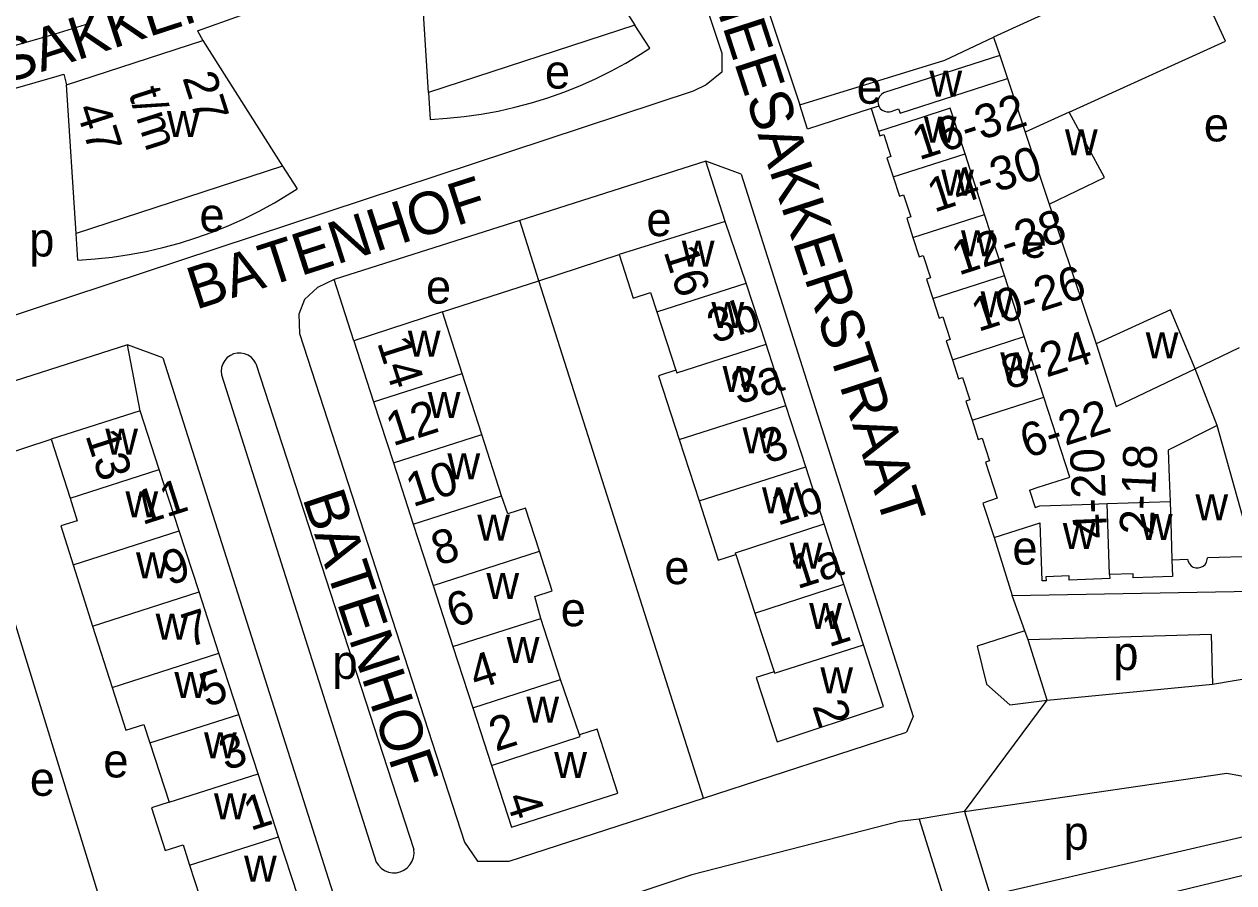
# Model space of a CAD drawing. Extents: x 159261 to 160849, y 382514 to 384534.
# Drawn here: x 159465.8 to 159608.7, y 383871.6 to 383973 of the extents above; entities that cross this region are included whole.
import ezdxf

# ---------------------------------------------------------------- set-up
doc = ezdxf.new("R2010")
doc.units = 0
for name, color, linetype in [('BLT_Basislijn', 7, 'Continuous'), ('BLT_Bebouwing', 7, 'Continuous'), ('BLT_Centroide', 7, 'Continuous'), ('BLT_Huisnummer', 7, 'Continuous'), ('BLT_Huisnummer_ tussenligend', 7, 'Continuous'), ('BLT_Huisnummer_reeks', 7, 'Continuous'), ('BLT_Onderverdeling_panden', 7, 'Continuous'), ('BLT_Straatnaam', 7, 'Continuous'), ('BLT_Vlakafsluiter', 7, 'Continuous')]:
    doc.layers.add(name, color=color, linetype=linetype)

msp = doc.modelspace()

# ---------------------------------------------------------------- linework, layer by layer
at = {"layer": 'BLT_Basislijn'}
for p, q in [((159486.27, 383972.23), (159486.92, 383971.08)), ((159539.7, 383970.18), (159537.94, 383972.9)), ((159470.51, 383967.12), (159470.82, 383965.85)), ((159513.56, 383964.95), (159513.76, 383961.78)), ((159566.75, 383963.34), (159565.83, 383963.05)), ((159565.83, 383963.05), (159566.72, 383960.35)), ((159546.3, 383956.85), (159524.34, 383949.84)), ((159550.49, 383955.29), (159546.3, 383956.85)), ((159548.59, 383949.7), (159546.3, 383956.85)), ((159496.32, 383956.25), (159498.05, 383953.56)), ((159586.88, 383951.77), (159592.41, 383935.27)), ((159526.61, 383942.71), (159524.34, 383949.84)), ((159472.15, 383945.16), (159471.94, 383948.3)), ((159526.61, 383942.71), (159536.09, 383945.81)), ((159504.74, 383935.61), (159502.43, 383942.85)), ((159515.2, 383939.05), (159526.61, 383942.71)), ((159546.06, 383881.62), (159526.61, 383942.71)), ((159478.01, 383935.15), (159456.04, 383928.14)), ((159482.19, 383933.6), (159478.01, 383935.15)), ((159479.51, 383927.34), (159478.01, 383935.15)), ((159604.09, 383932.33), (159609.33, 383934.84)), ((159606.71, 383925.63), (159604.09, 383932.33)), ((159459, 383920.75), (159469.01, 383924)), ((159477.76, 383859.92), (159459.94, 383917.82)), ((159580.37, 383912.39), (159582.49, 383905.53)), ((159584, 383901.36), (159582.49, 383905.53)), ((159584.39, 383900.29), (159584, 383901.36)), ((159605.98, 383900.92), (159584.39, 383900.29)), ((159605.98, 383900.92), (159606.15, 383895.08)), ((159586.64, 383893.19), (159584.39, 383900.29)), ((159546.06, 383881.62), (159570.02, 383889.39)), ((159576.87, 383880.02), (159571.53, 383879.14))]:
    msp.add_line(p, q, dxfattribs=at)
for points in [[(159539.48, 383995.83), (159548.21, 383969.61), (159548.21, 383967.35), (159546.34, 383965.85), (159544.84, 383965.1)], [(159486.27, 383972.23), (159491.37, 383974.05), (159496.45, 383975.95), (159501.49, 383977.92), (159506.5, 383979.96), (159511.49, 383982.08), (159512.44, 383982.5)], [(159559.38, 383977.05), (159553.49, 383975.26), (159557.4, 383963.49)], [(159432.92, 383963.01), (159438.12, 383964.03), (159443.3, 383965.12), (159448.47, 383966.29), (159453.62, 383967.53), (159458.75, 383968.86), (159463.86, 383970.26), (159468.95, 383971.74), (159473.57, 383973.15)], [(159557.4, 383963.49), (159574.56, 383968.78), (159580.29, 383971.51)], [(159513.76, 383961.78), (159515.78, 383961.91), (159517.79, 383962.11), (159519.79, 383962.4), (159521.78, 383962.76), (159523.76, 383963.21), (159525.71, 383963.73), (159527.64, 383964.33), (159529.55, 383965), (159531.43, 383965.75), (159533.28, 383966.58), (159535.09, 383967.47), (159536.87, 383968.44), (159538.61, 383969.47), (159539.7, 383970.18)], [(159443.48, 383960.15), (159448.77, 383961.34), (159454.03, 383962.61), (159459.27, 383963.96), (159464.5, 383965.38), (159469.7, 383966.88), (159470.51, 383967.12)], [(159544.84, 383965.1), (159432.28, 383927.93), (159430.03, 383927.56), (159427.78, 383927.93), (159425.9, 383928.68), (159423.65, 383935.07), (159417.03, 383955.37)], [(159565.83, 383963.05), (159558.32, 383960.64), (159557.4, 383963.49)], [(159550.49, 383955.29), (159570.82, 383891.26), (159570.02, 383889.39)], [(159472.15, 383945.16), (159474.18, 383945.3), (159476.2, 383945.51), (159478.22, 383945.81), (159480.21, 383946.18), (159482.2, 383946.64), (159484.16, 383947.17), (159486.1, 383947.77), (159488.02, 383948.46), (159489.9, 383949.21), (159491.76, 383950.04), (159493.58, 383950.95), (159495.37, 383951.92), (159497.11, 383952.97), (159498.05, 383953.56)], [(159524.34, 383949.84), (159502.43, 383942.85)], [(159502.43, 383942.85), (159500.47, 383941.93), (159498.92, 383940.52), (159498.25, 383938.79), (159498.33, 383936.49), (159517.83, 383876.42), (159519.34, 383874.17), (159523.09, 383874.17), (159546.06, 383881.62)], [(159493.16, 383932.96), (159492.95, 383933.32), (159492.65, 383933.64), (159492.27, 383933.91), (159491.84, 383934.09), (159491.39, 383934.17), (159490.95, 383934.16), (159490.54, 383934.07), (159490.16, 383933.9), (159489.8, 383933.64), (159489.49, 383933.3), (159489.26, 383932.9), (159489.12, 383932.46), (159489.08, 383932.02), (159489.12, 383931.6)], [(159482.19, 383933.6), (159502.53, 383869.56), (159501.72, 383867.69)], [(159493.16, 383932.96), (159511.82, 383875.52)], [(159489.12, 383931.6), (159507.39, 383874.05)], [(159582.49, 383905.53), (159610.88, 383906.06), (159611.04, 383910.16)], [(159584, 383901.36), (159578.35, 383899.57), (159579.47, 383895.05), (159582.22, 383892.62), (159586.64, 383893.19)], [(159586.64, 383893.19), (159606.15, 383895.08)], [(159606.15, 383895.08), (159611.26, 383895.92)], [(159576.87, 383880.02), (159607.84, 383884.57), (159613.4, 383883.55), (159615.78, 383881.39), (159617.5, 383878.84)], [(159576.87, 383880.02), (159579.79, 383870.52), (159580.1, 383870.2), (159617.5, 383878.84)], [(159571.53, 383879.14), (159574.49, 383869.54), (159573.51, 383869.33), (159573.04, 383868.91), (159539.85, 383861.58), (159533.8, 383859.61), (159521.41, 383853.83), (159520.77, 383854.16), (159518.2, 383863.73)], [(159571.53, 383879.14), (159569.17, 383878.86), (159544.68, 383872.53), (159518.2, 383863.73)], [(159507.39, 383874.05), (159507.64, 383873.67), (159507.97, 383873.33), (159508.38, 383873.06), (159508.84, 383872.87), (159509.32, 383872.79), (159509.79, 383872.8), (159510.23, 383872.9), (159510.64, 383873.08), (159511.03, 383873.36), (159511.37, 383873.71), (159511.62, 383874.14), (159511.79, 383874.6), (159511.85, 383875.07), (159511.82, 383875.52)], [(159585.27, 383853.34), (159584.12, 383856.18), (159581.66, 383865.68), (159618.88, 383874.73)]]:
    msp.add_lwpolyline(points, dxfattribs=at)
at = {"layer": 'BLT_Bebouwing'}
for p, q in [((159528.54, 383987.73), (159537.94, 383972.9)), ((159513.56, 383964.95), (159512.44, 383982.5)), ((159537.94, 383972.9), (159513.56, 383964.95)), ((159470.82, 383965.85), (159486.92, 383971.08)), ((159486.92, 383971.08), (159496.32, 383956.25)), ((159580.29, 383971.51), (159581.04, 383969.34)), ((159581.04, 383969.34), (159567.31, 383964.9)), ((159581.93, 383966.6), (159582.48, 383964.94)), ((159471.94, 383948.3), (159470.82, 383965.85)), ((159582.48, 383964.94), (159584.04, 383960.27)), ((159579.24, 383950.56), (159576.93, 383957.73)), ((159496.32, 383956.25), (159471.94, 383948.3)), ((159548.59, 383949.7), (159536.09, 383945.81)), ((159581.58, 383943.35), (159579.24, 383950.56)), ((159583.92, 383936.12), (159581.58, 383943.35)), ((159515.2, 383939.05), (159504.74, 383935.61)), ((159586.23, 383928.98), (159583.92, 383936.12)), ((159479.51, 383927.34), (159469.01, 383924)), ((159481.76, 383920.41), (159479.51, 383927.34)), ((159469.01, 383924), (159471.23, 383917.04)), ((159484.11, 383913.18), (159481.76, 383920.41)), ((159593.73, 383916.39), (159601.14, 383916.64)), ((159486.46, 383905.96), (159484.11, 383913.18)), ((159611.04, 383910.16), (159605.55, 383909.98)), ((159471.58, 383909.17), (159473.88, 383901.93)), ((159488.81, 383898.73), (159486.46, 383905.96)), ((159473.88, 383901.93), (159476.19, 383894.69)), ((159491.16, 383891.5), (159488.81, 383898.73)), ((159493.44, 383884.49), (159491.16, 383891.5)), ((159480.66, 383888.14), (159482.93, 383881.13)), ((159495.86, 383877.04), (159493.44, 383884.49))]:
    msp.add_line(p, q, dxfattribs=at)
for points in [[(159619.1, 383987.92), (159611.22, 383985.63), (159580.29, 383971.51)], [(159589.23, 383962.63), (159607.68, 383971.03), (159605.6, 383975.56)], [(159568.19, 383962.73), (159569.09, 383963.02), (159569.26, 383962.5), (159581.93, 383966.6)], [(159567.31, 383964.9), (159567.06, 383964.73), (159566.85, 383964.51), (159566.71, 383964.23), (159566.65, 383963.93), (159566.66, 383963.63), (159566.75, 383963.34)], [(159576.93, 383957.73), (159575.19, 383963.1), (159571.48, 383961.9), (159566.72, 383960.35)], [(159566.75, 383963.34), (159566.92, 383963.08), (159567.14, 383962.88), (159567.41, 383962.74), (159567.71, 383962.67), (159568.02, 383962.69), (159568.19, 383962.73)], [(159586.88, 383951.77), (159593.42, 383954.92), (159589.23, 383962.63)], [(159566.72, 383960.35), (159566.88, 383959.85), (159567.33, 383960), (159568.17, 383957.39), (159567.71, 383957.24), (159568.45, 383954.98)], [(159584.04, 383960.27), (159586.88, 383951.77)], [(159568.45, 383954.98), (159569.18, 383952.71), (159569.66, 383952.87), (159570.51, 383950.25), (159570.04, 383950.1), (159570.78, 383947.82)], [(159551.08, 383942.43), (159548.59, 383949.7)], [(159570.78, 383947.82), (159571.51, 383945.55), (159572, 383945.71), (159572.86, 383943.07), (159572.37, 383942.91), (159573.11, 383940.61)], [(159536.09, 383945.81), (159537.73, 383940.68), (159539.8, 383941.35), (159540.54, 383939.06)], [(159553.43, 383935.21), (159551.08, 383942.43)], [(159573.11, 383940.61), (159573.86, 383938.31), (159574.31, 383938.46), (159575.18, 383935.78), (159574.71, 383935.62), (159575.43, 383933.38)], [(159517.53, 383931.77), (159515.2, 383939.05)], [(159540.54, 383939.06), (159542.78, 383932.16)], [(159604.09, 383932.33), (159601.21, 383939.27), (159592.41, 383935.27)], [(159504.74, 383935.61), (159507.07, 383928.43)], [(159555.77, 383927.98), (159553.43, 383935.21)], [(159592.41, 383935.27), (159594.77, 383927.87), (159604.09, 383932.33)], [(159575.43, 383933.38), (159576.16, 383931.13), (159576.64, 383931.28), (159577.48, 383928.66), (159577.02, 383928.51), (159577.76, 383926.24)], [(159519.86, 383924.54), (159517.53, 383931.77)], [(159542.78, 383932.16), (159540.73, 383931.49), (159543.17, 383923.95)], [(159507.07, 383928.43), (159509.41, 383921.2)], [(159558.12, 383920.75), (159555.77, 383927.98)], [(159584.55, 383917.99), (159585.58, 383918.33), (159589.29, 383919.53), (159586.23, 383928.98)], [(159577.76, 383926.24), (159578.49, 383923.98), (159578.96, 383924.13), (159579.83, 383921.45), (159579.36, 383921.3), (159580.74, 383917.04), (159579.02, 383916.44), (159580.37, 383912.39)], [(159606.71, 383925.63), (159600.91, 383922.7), (159601.02, 383919.47), (159601.14, 383916.64)], [(159610.17, 383913.27), (159609.69, 383914.97), (159606.71, 383925.63)], [(159522.18, 383917.3), (159519.86, 383924.54)], [(159543.17, 383923.95), (159545.52, 383916.72)], [(159509.41, 383921.2), (159511.75, 383913.97)], [(159560.31, 383914), (159558.12, 383920.75)], [(159584.55, 383917.99), (159585.22, 383915.94), (159585.75, 383916.12), (159590.75, 383916.29), (159593.73, 383916.39)], [(159471.23, 383917.04), (159472.08, 383914.37), (159470.13, 383913.75), (159471.58, 383909.17)], [(159526.67, 383910.76), (159525.02, 383915.84), (159522.95, 383915.17), (159522.18, 383917.3)], [(159545.52, 383916.72), (159547.78, 383909.73), (159549.86, 383910.4)], [(159511.75, 383913.97), (159514.1, 383906.74)], [(159562.63, 383906.86), (159560.31, 383914)], [(159580.37, 383912.39), (159585.82, 383914.13)], [(159594.01, 383908.01), (159594.03, 383907.53), (159589.24, 383907.37), (159589.22, 383907.85), (159586.49, 383907.76), (159586.51, 383907.29), (159586.05, 383907.28), (159585.82, 383914.13)], [(159526.83, 383902.83), (159526.11, 383905.42), (159528.18, 383906.09), (159526.67, 383910.76)], [(159549.86, 383910.4), (159552.11, 383903.47)], [(159601.37, 383909.77), (159601.44, 383907.8), (159596.8, 383907.64), (159596.78, 383908.1), (159594.01, 383908.01)], [(159601.37, 383909.77), (159603.2, 383909.84), (159603.27, 383909.54), (159603.42, 383909.27), (159603.63, 383909.05), (159603.89, 383908.89), (159604.18, 383908.8), (159604.49, 383908.8), (159604.79, 383908.87), (159605.06, 383909.01), (159605.28, 383909.22), (159605.44, 383909.49), (159605.53, 383909.78), (159605.55, 383909.98)], [(159514.1, 383906.74), (159516.44, 383899.51)], [(159564.94, 383899.73), (159562.63, 383906.86)], [(159529.16, 383895.6), (159526.83, 383902.83)], [(159552.11, 383903.47), (159554.37, 383896.52)], [(159516.44, 383899.51), (159518.78, 383892.28)], [(159554.37, 383896.52), (159552.28, 383895.84), (159554.74, 383888.25), (159567.31, 383892.44), (159564.94, 383899.73)], [(159531.41, 383889.07), (159529.16, 383895.6)], [(159476.19, 383894.69), (159477.8, 383889.63), (159479.95, 383890.31), (159480.66, 383888.14)], [(159518.78, 383892.28), (159520.99, 383885.45)], [(159520.99, 383885.45), (159523.35, 383878.17), (159535.94, 383882.18), (159533.5, 383889.74), (159531.41, 383889.07)], [(159482.93, 383881.13), (159480.84, 383880.45), (159482.48, 383875.41), (159484.57, 383876.09), (159485.35, 383873.68)], [(159485.35, 383873.68), (159487.69, 383866.45), (159498.16, 383869.95), (159495.86, 383877.04)]]:
    msp.add_lwpolyline(points, dxfattribs=at)
at = {"layer": 'BLT_Onderverdeling_panden'}
for p, q in [((159581.04, 383969.34), (159581.93, 383966.6)), ((159589.23, 383962.63), (159584.04, 383960.27)), ((159568.45, 383954.98), (159576.93, 383957.73)), ((159570.78, 383947.82), (159579.24, 383950.56)), ((159540.54, 383939.06), (159551.08, 383942.43)), ((159573.11, 383940.61), (159581.58, 383943.35)), ((159575.43, 383933.38), (159583.92, 383936.12)), ((159507.07, 383928.43), (159517.53, 383931.77)), ((159543.17, 383923.95), (159555.77, 383927.98)), ((159577.76, 383926.24), (159586.23, 383928.98)), ((159509.41, 383921.2), (159519.86, 383924.54)), ((159471.23, 383917.04), (159481.76, 383920.41)), ((159545.52, 383916.72), (159558.12, 383920.75)), ((159511.75, 383913.97), (159522.18, 383917.3)), ((159594.01, 383908.01), (159593.73, 383916.39)), ((159471.58, 383909.17), (159484.11, 383913.18)), ((159514.1, 383906.74), (159526.67, 383910.76)), ((159552.11, 383903.47), (159562.63, 383906.86)), ((159473.88, 383901.93), (159486.46, 383905.96)), ((159516.44, 383899.51), (159526.83, 383902.83)), ((159476.19, 383894.69), (159488.81, 383898.73)), ((159518.78, 383892.28), (159529.16, 383895.6)), ((159480.66, 383888.14), (159491.16, 383891.5)), ((159482.93, 383881.13), (159493.44, 383884.49)), ((159485.35, 383873.68), (159495.86, 383877.04))]:
    msp.add_line(p, q, dxfattribs=at)
for points in [[(159542.78, 383932.16), (159542.89, 383931.83), (159553.43, 383935.21)], [(159601.14, 383916.64), (159601.27, 383912.8), (159601.37, 383909.77)], [(159549.86, 383910.4), (159549.81, 383910.58), (159560.31, 383914)], [(159554.37, 383896.52), (159554.42, 383896.35), (159564.94, 383899.73)], [(159520.99, 383885.45), (159531.47, 383888.9), (159531.41, 383889.07)]]:
    msp.add_lwpolyline(points, dxfattribs=at)
at = {"layer": 'BLT_Vlakafsluiter'}
msp.add_line((159576.87, 383880.02), (159586.64, 383893.19), dxfattribs=at)

# ---------------------------------------------------------------- texts
at = {"layer": 'BLT_Centroide'}
for s, p in [('e', (159527.31, 383965.42)), ('e', (159564.14, 383963.63)), ('w', (159572.72, 383964.45)), ('w', (159482.67, 383959.69)), ('e', (159605.13, 383959.18)), ('w', (159572.07, 383959.03)), ('w', (159588.73, 383957.53)), ('w', (159574.11, 383952.78)), ('e', (159486.51, 383948.51)), ('e', (159539.3, 383947.99)), ('p', (159466.4, 383945.59)), ('w', (159576.45, 383945.59)), ('e', (159583.62, 383945.43)), ('w', (159543.48, 383944.38)), ('e', (159513.26, 383940.02)), ('w', (159578.77, 383938.38)), ('w', (159546.98, 383937.12)), ('w', (159511.12, 383933.75)), ('w', (159598.27, 383933.56)), ('w', (159581.09, 383931.19)), ('w', (159548.3, 383929.56)), ('w', (159513.47, 383926.5)), ('w', (159475.39, 383922.19)), ('w', (159550.65, 383922.34)), ('w', (159515.8, 383919.25)), ('w', (159552.95, 383915.25)), ('w', (159477.77, 383914.78)), ('w', (159604.14, 383914.43)), ('w', (159519.32, 383912.03)), ('w', (159597.58, 383912.09)), ('w', (159588.47, 383911.05)), ('e', (159582.52, 383909.19)), ('w', (159556.21, 383908.72)), ('w', (159479.02, 383907.56)), ('e', (159541.41, 383906.88)), ('w', (159520.4, 383905.12)), ('e', (159529.18, 383901.91)), ('w', (159558.52, 383901.59)), ('w', (159481.34, 383900.31)), ('w', (159522.8, 383897.56)), ('p', (159594.44, 383896.73)), ('p', (159502.21, 383895.69)), ('w', (159483.55, 383893.44)), ('w', (159559.84, 383894)), ('w', (159525.12, 383890.53)), ('w', (159487.05, 383886.31)), ('e', (159475.16, 383884.05)), ('w', (159528.41, 383883.97)), ('e', (159466.48, 383881.88)), ('w', (159488.23, 383879.09)), ('p', (159588.56, 383875.5)), ('w', (159491.78, 383871.75))]:
    msp.add_text(s, height=4, dxfattribs=at).set_placement(p)
at = {"layer": 'BLT_Huisnummer'}
for s, rotation, p in [('16', 287.744, (159541.3, 383946.18)), ('3b', 17.7443, (159547.27, 383935.29)), ('14', 287.744, (159507.47, 383935.42)), ('12', 17.7443, (159509.35, 383923.15)), ('13', 287.744, (159473.01, 383924.47)), ('11', 17.7443, (159479.77, 383913.85)), ('1b', 17.7443, (159554.79, 383913.76)), ('8', 17.7443, (159514.68, 383909.01)), ('1', 17.7443, (159560.84, 383899.41)), ('5', 17.7443, (159487.31, 383892.33)), ('2', 287.744, (159558.86, 383892.5)), ('2', 17.7443, (159521.49, 383887.08)), ('1', 17.7443, (159492.54, 383877.72)), ('4', 287.744, (159522.63, 383881.66))]:
    msp.add_text(s, height=4, rotation=rotation, dxfattribs=at).set_placement(p)
at = {"layer": 'BLT_Huisnummer_ tussenligend'}
for s, p in [('3a', (159550.12, 383928.05)), ('3', (159553.55, 383921.08)), ('10', (159511.71, 383915.96)), ('9', (159482.88, 383906.69)), ('1a', (159557.12, 383906.27)), ('6', (159516.47, 383901.7)), ('7', (159485.24, 383899.38)), ('4', (159519.16, 383894.38)), ('3', (159489.61, 383884.83))]:
    msp.add_text(s, height=4, rotation=17.7443, dxfattribs=at).set_placement(p)
at = {"layer": 'BLT_Huisnummer_reeks'}
for s, rotation, p in [('27', 287.7057, (159484.47, 383966.71)), ('t/m', 287.7057, (159478.1, 383964.91)), ('16-32', 17.9511, (159571.5, 383956.93)), ('47', 287.7049, (159471.87, 383963.06)), ('14-30', 17.9463, (159573.29, 383950.76)), ('12-28', 17.934, (159576.18, 383943.32)), ('10-26', 17.934, (159578.49, 383936.66)), ('8-24', 17.9407, (159582.02, 383929.81)), ('6-22', 17.948, (159584.23, 383921.72)), ('4-20', 92.3428, (159593.74, 383912.33)), ('2-18', 87.2873, (159599.15, 383912.62))]:
    msp.add_text(s, height=4, rotation=rotation, dxfattribs=at).set_placement(p)
at = {"layer": 'BLT_Straatnaam'}
for s, height, rotation, p in [('HEESAKKERSTRAAT', 4.9999, 18.0521, (159450.5, 383961.71)), ('HEESAKKERSTRAAT', 5, 288.0521, (159546.76, 383977.34)), ('BATENHOF', 5, 17.8259, (159486.08, 383939.27)), ('BATENHOF', 5, 288.2846, (159498.65, 383917.04))]:
    msp.add_text(s, height=height, rotation=rotation, dxfattribs=at).set_placement(p)

doc.saveas('drawing.dxf')
